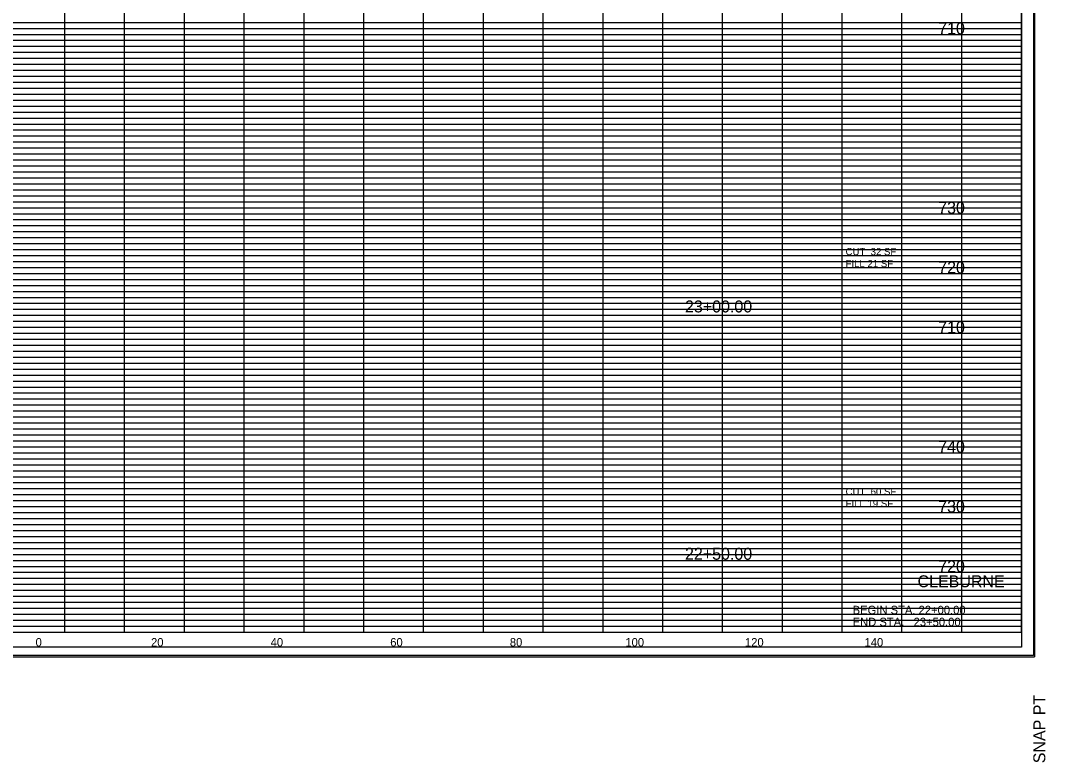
# Model space of a CAD drawing. Extents: x -200 to 1324, y -325 to 1497.
# Drawn here: x 1152.6 to 1324, y 1248.2 to 1372.3 of the extents above; entities that cross this region are included whole.
import ezdxf

# ---------------------------------------------------------------- set-up
doc = ezdxf.new("R2010")
doc.units = 0
for name, color, linetype in [('DESIGN - SHEET - Corner Text', 7, 'Continuous'), ('DESIGN - SHEET - Light Grid', 7, 'Continuous'), ('DESIGN - SHEET - Linework', 7, 'Continuous'), ('DESIGN - SHEET - Plot Shape', 7, 'Continuous'), ('DESIGN - TYPICAL - Text', 7, 'Continuous')]:
    doc.layers.add(name, color=color, linetype=linetype)

msp = doc.modelspace()

# ---------------------------------------------------------------- linework, layer by layer
at = {"layer": 'DESIGN - SHEET - Light Grid'}
for p, q in [((1080, 1372), (1160, 1372)), ((1160, 1372), (1240, 1372)), ((1240, 1372), (1320, 1372)), ((1080, 1371), (1160, 1371)), ((1160, 1371), (1240, 1371)), ((1240, 1371), (1320, 1371)), ((1080, 1369), (1160, 1369)), ((1080, 1368), (1160, 1368)), ((1160, 1369), (1240, 1369)), ((1160, 1368), (1240, 1368)), ((1240, 1369), (1320, 1369)), ((1240, 1368), (1320, 1368)), ((1080, 1367), (1160, 1367)), ((1160, 1367), (1240, 1367)), ((1240, 1367), (1320, 1367)), ((1080, 1366), (1160, 1366)), ((1080, 1365), (1160, 1365)), ((1160, 1366), (1240, 1366)), ((1160, 1365), (1240, 1365)), ((1240, 1366), (1320, 1366)), ((1240, 1365), (1320, 1365)), ((1080, 1364), (1160, 1364)), ((1080, 1363), (1160, 1363)), ((1160, 1364), (1240, 1364)), ((1160, 1363), (1240, 1363)), ((1240, 1364), (1320, 1364)), ((1240, 1363), (1320, 1363)), ((1080, 1362), (1160, 1362)), ((1080, 1361), (1160, 1361)), ((1160, 1362), (1240, 1362)), ((1160, 1361), (1240, 1361)), ((1240, 1362), (1320, 1362)), ((1240, 1361), (1320, 1361)), ((1080, 1359), (1160, 1359)), ((1080, 1358), (1160, 1358)), ((1160, 1359), (1240, 1359)), ((1160, 1358), (1240, 1358)), ((1240, 1359), (1320, 1359)), ((1240, 1358), (1320, 1358)), ((1080, 1357), (1160, 1357)), ((1080, 1356), (1160, 1356)), ((1160, 1357), (1240, 1357)), ((1160, 1356), (1240, 1356)), ((1240, 1357), (1320, 1357)), ((1240, 1356), (1320, 1356)), ((1080, 1355), (1160, 1355)), ((1160, 1355), (1240, 1355)), ((1240, 1355), (1320, 1355)), ((1080, 1354), (1160, 1354)), ((1080, 1353), (1160, 1353)), ((1160, 1354), (1240, 1354)), ((1160, 1353), (1240, 1353)), ((1240, 1354), (1320, 1354)), ((1240, 1353), (1320, 1353)), ((1080, 1352), (1160, 1352)), ((1080, 1351), (1160, 1351)), ((1160, 1352), (1240, 1352)), ((1160, 1351), (1240, 1351)), ((1240, 1352), (1320, 1352)), ((1240, 1351), (1320, 1351)), ((1080, 1349), (1160, 1349)), ((1160, 1349), (1240, 1349)), ((1240, 1349), (1320, 1349)), ((1080, 1348), (1160, 1348)), ((1160, 1348), (1240, 1348)), ((1240, 1348), (1320, 1348)), ((1080, 1347), (1160, 1347)), ((1080, 1346), (1160, 1346)), ((1160, 1347), (1240, 1347)), ((1160, 1346), (1240, 1346)), ((1240, 1347), (1320, 1347)), ((1240, 1346), (1320, 1346)), ((1080, 1345), (1160, 1345)), ((1080, 1344), (1160, 1344)), ((1160, 1345), (1240, 1345)), ((1160, 1344), (1240, 1344)), ((1240, 1345), (1320, 1345)), ((1240, 1344), (1320, 1344)), ((1080, 1343), (1160, 1343)), ((1160, 1343), (1240, 1343)), ((1240, 1343), (1320, 1343)), ((1080, 1342), (1160, 1342)), ((1080, 1341), (1160, 1341)), ((1160, 1342), (1240, 1342)), ((1160, 1341), (1240, 1341)), ((1240, 1342), (1320, 1342)), ((1240, 1341), (1320, 1341)), ((1080, 1339), (1160, 1339)), ((1160, 1339), (1240, 1339)), ((1240, 1339), (1320, 1339)), ((1080, 1338), (1160, 1338)), ((1080, 1337), (1160, 1337)), ((1160, 1338), (1240, 1338)), ((1160, 1337), (1240, 1337)), ((1240, 1338), (1320, 1338)), ((1240, 1337), (1320, 1337)), ((1080, 1336), (1160, 1336)), ((1160, 1336), (1240, 1336)), ((1240, 1336), (1320, 1336)), ((1080, 1335), (1160, 1335)), ((1080, 1334), (1160, 1334)), ((1160, 1335), (1240, 1335)), ((1160, 1334), (1240, 1334)), ((1240, 1335), (1320, 1335)), ((1240, 1334), (1320, 1334)), ((1080, 1333), (1160, 1333)), ((1080, 1332), (1160, 1332)), ((1160, 1333), (1240, 1333)), ((1160, 1332), (1240, 1332)), ((1240, 1333), (1320, 1333)), ((1240, 1332), (1320, 1332)), ((1080, 1331), (1160, 1331)), ((1160, 1331), (1240, 1331)), ((1240, 1331), (1320, 1331)), ((1080, 1329), (1160, 1329)), ((1160, 1329), (1240, 1329)), ((1240, 1329), (1320, 1329)), ((1080, 1328), (1160, 1328)), ((1080, 1327), (1160, 1327)), ((1160, 1328), (1240, 1328)), ((1160, 1327), (1240, 1327)), ((1240, 1328), (1320, 1328)), ((1240, 1327), (1320, 1327)), ((1080, 1326), (1160, 1326)), ((1080, 1325), (1160, 1325)), ((1160, 1326), (1240, 1326)), ((1160, 1325), (1240, 1325)), ((1240, 1326), (1320, 1326)), ((1240, 1325), (1320, 1325)), ((1080, 1324), (1160, 1324)), ((1160, 1324), (1240, 1324)), ((1240, 1324), (1320, 1324)), ((1080, 1323), (1160, 1323)), ((1080, 1322), (1160, 1322)), ((1160, 1323), (1240, 1323)), ((1160, 1322), (1240, 1322)), ((1240, 1323), (1320, 1323)), ((1240, 1322), (1320, 1322)), ((1080, 1321), (1160, 1321)), ((1160, 1321), (1240, 1321)), ((1240, 1321), (1320, 1321)), ((1080, 1319), (1160, 1319)), ((1160, 1319), (1240, 1319)), ((1240, 1319), (1320, 1319)), ((1080, 1318), (1160, 1318)), ((1080, 1317), (1160, 1317)), ((1160, 1318), (1240, 1318)), ((1160, 1317), (1240, 1317)), ((1240, 1318), (1320, 1318)), ((1240, 1317), (1320, 1317)), ((1080, 1316), (1160, 1316)), ((1080, 1315), (1160, 1315)), ((1160, 1316), (1240, 1316)), ((1160, 1315), (1240, 1315)), ((1240, 1316), (1320, 1316)), ((1240, 1315), (1320, 1315)), ((1080, 1314), (1160, 1314)), ((1080, 1313), (1160, 1313)), ((1160, 1314), (1240, 1314)), ((1160, 1313), (1240, 1313)), ((1240, 1314), (1320, 1314)), ((1240, 1313), (1320, 1313)), ((1080, 1312), (1160, 1312)), ((1160, 1312), (1240, 1312)), ((1240, 1312), (1320, 1312)), ((1080, 1311), (1160, 1311)), ((1160, 1311), (1240, 1311)), ((1240, 1311), (1320, 1311)), ((1080, 1309), (1160, 1309)), ((1080, 1308), (1160, 1308)), ((1160, 1309), (1240, 1309)), ((1160, 1308), (1240, 1308)), ((1240, 1309), (1320, 1309)), ((1240, 1308), (1320, 1308)), ((1080, 1307), (1160, 1307)), ((1160, 1307), (1240, 1307)), ((1240, 1307), (1320, 1307)), ((1080, 1306), (1160, 1306)), ((1080, 1305), (1160, 1305)), ((1160, 1306), (1240, 1306)), ((1160, 1305), (1240, 1305)), ((1240, 1306), (1320, 1306)), ((1240, 1305), (1320, 1305)), ((1080, 1304), (1160, 1304)), ((1080, 1303), (1160, 1303)), ((1160, 1304), (1240, 1304)), ((1160, 1303), (1240, 1303)), ((1240, 1304), (1320, 1304)), ((1240, 1303), (1320, 1303)), ((1080, 1302), (1160, 1302)), ((1080, 1301), (1160, 1301)), ((1160, 1302), (1240, 1302)), ((1160, 1301), (1240, 1301)), ((1240, 1302), (1320, 1302)), ((1240, 1301), (1320, 1301)), ((1080, 1299), (1160, 1299)), ((1080, 1298), (1160, 1298)), ((1160, 1299), (1240, 1299)), ((1160, 1298), (1240, 1298)), ((1240, 1299), (1320, 1299)), ((1240, 1298), (1320, 1298)), ((1080, 1297), (1160, 1297)), ((1080, 1296), (1160, 1296)), ((1160, 1297), (1240, 1297)), ((1160, 1296), (1240, 1296)), ((1240, 1297), (1320, 1297)), ((1240, 1296), (1320, 1296)), ((1080, 1295), (1160, 1295)), ((1160, 1295), (1240, 1295)), ((1240, 1295), (1320, 1295)), ((1080, 1294), (1160, 1294)), ((1080, 1293), (1160, 1293)), ((1160, 1294), (1240, 1294)), ((1160, 1293), (1240, 1293)), ((1240, 1294), (1320, 1294)), ((1240, 1293), (1320, 1293)), ((1080, 1292), (1160, 1292)), ((1080, 1291), (1160, 1291)), ((1160, 1292), (1240, 1292)), ((1160, 1291), (1240, 1291)), ((1240, 1292), (1320, 1292)), ((1240, 1291), (1320, 1291)), ((1080, 1289), (1160, 1289)), ((1160, 1289), (1240, 1289)), ((1240, 1289), (1320, 1289)), ((1080, 1288), (1160, 1288)), ((1160, 1288), (1240, 1288)), ((1240, 1288), (1320, 1288)), ((1080, 1287), (1160, 1287)), ((1080, 1286), (1160, 1286)), ((1160, 1287), (1240, 1287)), ((1160, 1286), (1240, 1286)), ((1240, 1287), (1320, 1287)), ((1240, 1286), (1320, 1286)), ((1080, 1285), (1160, 1285)), ((1080, 1284), (1160, 1284)), ((1160, 1285), (1240, 1285)), ((1160, 1284), (1240, 1284)), ((1240, 1285), (1320, 1285)), ((1240, 1284), (1320, 1284)), ((1080, 1283), (1160, 1283)), ((1160, 1283), (1240, 1283)), ((1240, 1283), (1320, 1283)), ((1080, 1282), (1160, 1282)), ((1080, 1281), (1160, 1281)), ((1160, 1282), (1240, 1282)), ((1160, 1281), (1240, 1281)), ((1240, 1282), (1320, 1282)), ((1240, 1281), (1320, 1281)), ((1080, 1279), (1160, 1279)), ((1160, 1279), (1240, 1279)), ((1240, 1279), (1320, 1279)), ((1080, 1278), (1160, 1278)), ((1080, 1277), (1160, 1277)), ((1160, 1278), (1240, 1278)), ((1160, 1277), (1240, 1277)), ((1240, 1278), (1320, 1278)), ((1240, 1277), (1320, 1277)), ((1080, 1276), (1160, 1276)), ((1160, 1276), (1240, 1276)), ((1240, 1276), (1320, 1276)), ((1080, 1275), (1160, 1275)), ((1080, 1274), (1160, 1274)), ((1160, 1275), (1240, 1275)), ((1160, 1274), (1240, 1274)), ((1240, 1275), (1320, 1275)), ((1240, 1274), (1320, 1274)), ((1080, 1273), (1160, 1273)), ((1080, 1272), (1160, 1272)), ((1160, 1273), (1240, 1273)), ((1160, 1272), (1240, 1272)), ((1240, 1273), (1320, 1273)), ((1240, 1272), (1320, 1272)), ((1080, 1271), (1160, 1271)), ((1160, 1271), (1240, 1271)), ((1240, 1271), (1320, 1271))]:
    msp.add_line(p, q, dxfattribs=at)
at = {"layer": 'DESIGN - SHEET - Linework'}
for p, q in [((1322.17, 1484.14), (1322.17, 1265.86)), ((1160, 1270), (1160, 1480)), ((1170, 1270), (1170, 1480)), ((1180, 1270), (1180, 1480)), ((1190, 1270), (1190, 1480)), ((1200, 1270), (1200, 1480)), ((1210, 1270), (1210, 1480)), ((1220, 1270), (1220, 1480)), ((1230, 1270), (1230, 1480)), ((1240, 1270), (1240, 1480)), ((1250, 1270), (1250, 1480)), ((1260, 1270), (1260, 1480)), ((1270, 1270), (1270, 1480)), ((1280, 1270), (1280, 1470)), ((1290, 1270), (1290, 1470)), ((1300, 1270), (1300, 1470)), ((1310, 1270), (1310, 1470)), ((1000, 1370), (1320, 1370)), ((1000, 1360), (1320, 1360)), ((1000, 1350), (1320, 1350)), ((1000, 1340), (1320, 1340)), ((1000, 1330), (1320, 1330)), ((1000, 1320), (1320, 1320)), ((1000, 1310), (1320, 1310)), ((1000, 1300), (1320, 1300)), ((1000, 1290), (1320, 1290)), ((1000, 1280), (1320, 1280)), ((981.77, 1265.86), (1322.17, 1265.86))]:
    msp.add_line(p, q, dxfattribs=at)
msp.add_lwpolyline([(1000, 1480), (1000, 1270), (1320, 1270), (1320, 1480), (1000, 1480)], dxfattribs=at)
at = {"layer": 'DESIGN - SHEET - Plot Shape'}
for points in [[(981.97, 1483.94), (1321.97, 1483.94), (1321.97, 1266.06), (981.97, 1266.06)], [(991.5, 1480), (1320, 1480), (1320, 1267.5), (991.5, 1267.5)]]:
    msp.add_lwpolyline(points, close=True, dxfattribs=at)

# ---------------------------------------------------------------- texts
at = {"layer": 'DESIGN - SHEET - Corner Text'}
for s, height, p in [('CLEBURNE', 2, (1302.61, 1277.5)), ('BEGIN STA. 22+00.00', 1.4, (1291.75, 1273)), ('END STA.   23+50.00', 1.4, (1291.75, 1271))]:
    msp.add_text(s, height=height, dxfattribs=at).set_placement(p)
msp.add_text('SNAP PT  ', height=2, rotation=90, dxfattribs=at).set_placement((1323.97, 1248.06))
at = {"layer": 'DESIGN - TYPICAL - Text'}
for s, height, p in [('     710     ', 2, (1302.34, 1370)), ('     730     ', 2, (1302.34, 1340)), ('CUT  32 SF', 1.2, (1290.57, 1333.05)), ('FILL 21 SF', 1.2, (1290.57, 1331.05)), ('     720     ', 2, (1302.34, 1330)), ('     23+00.00     ', 2, (1260, 1323.48)), ('     710     ', 2, (1302.34, 1320)), ('     740     ', 2, (1302.34, 1300)), ('CUT  60 SF', 1.2, (1290.57, 1292.9)), ('FILL 19 SF', 1.2, (1290.57, 1290.9)), ('     730     ', 2, (1302.34, 1290)), ('     22+50.00     ', 2, (1260, 1282.1)), ('     720     ', 2, (1302.34, 1280)), ('     0     ', 1.4, (1152.51, 1267.6)), ('     0     ', 1.4, (1152.51, 1267.6)), ('     20     ', 1.4, (1171.82, 1267.6)), ('     40     ', 1.4, (1191.82, 1267.6)), ('     60     ', 1.4, (1211.82, 1267.6)), ('     80     ', 1.4, (1231.82, 1267.6)), ('     100     ', 1.4, (1251.14, 1267.6)), ('     120     ', 1.4, (1271.14, 1267.6)), ('     140     ', 1.4, (1291.14, 1267.6))]:
    msp.add_text(s, height=height, dxfattribs=at).set_placement(p)

doc.saveas('drawing.dxf')
